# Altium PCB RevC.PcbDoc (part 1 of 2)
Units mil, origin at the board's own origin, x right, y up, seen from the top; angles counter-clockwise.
Board outline 3110.24 x 2539.37 mil, 2 copper layers (Top Layer, Bottom Layer); 147 components, 154 nets, 636 pads, 215 vias.
Unrouted connection lines stored in the file: 2.
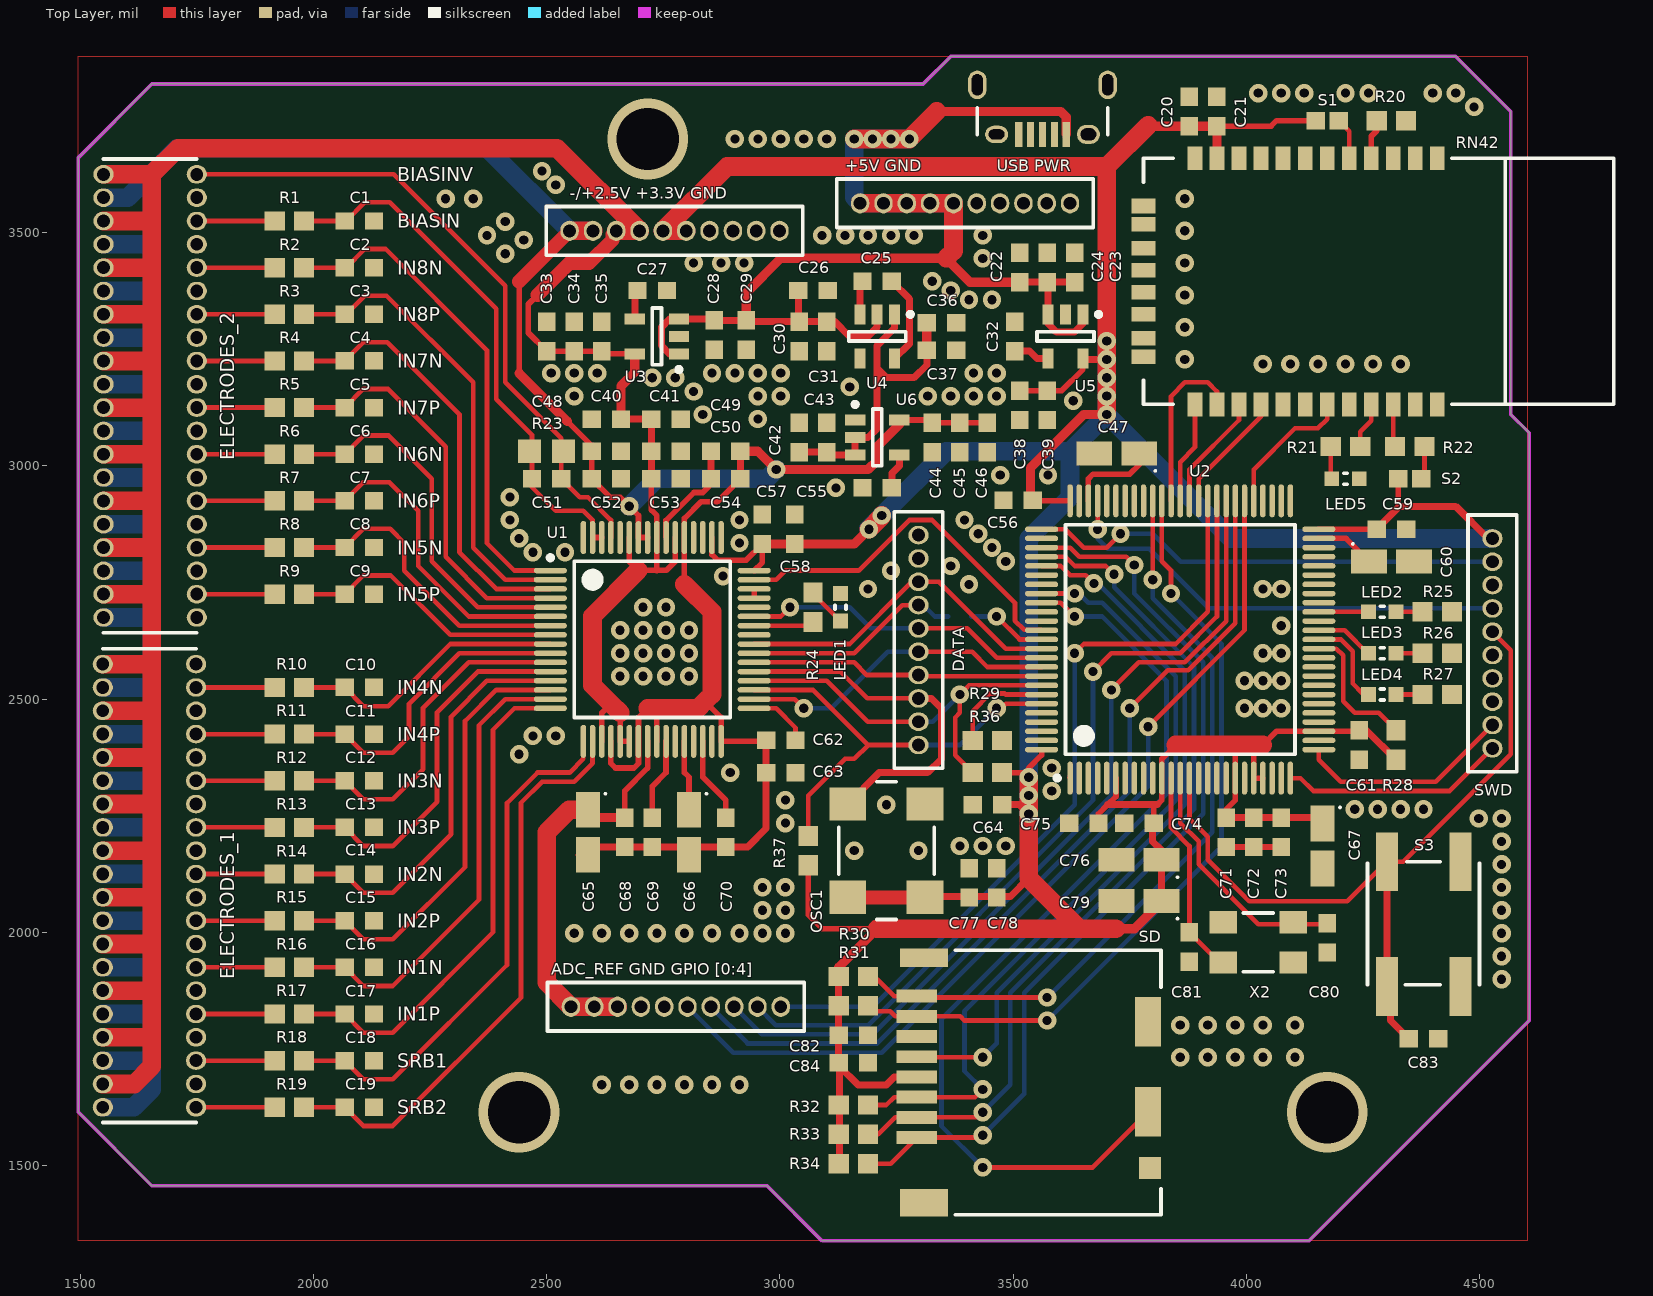
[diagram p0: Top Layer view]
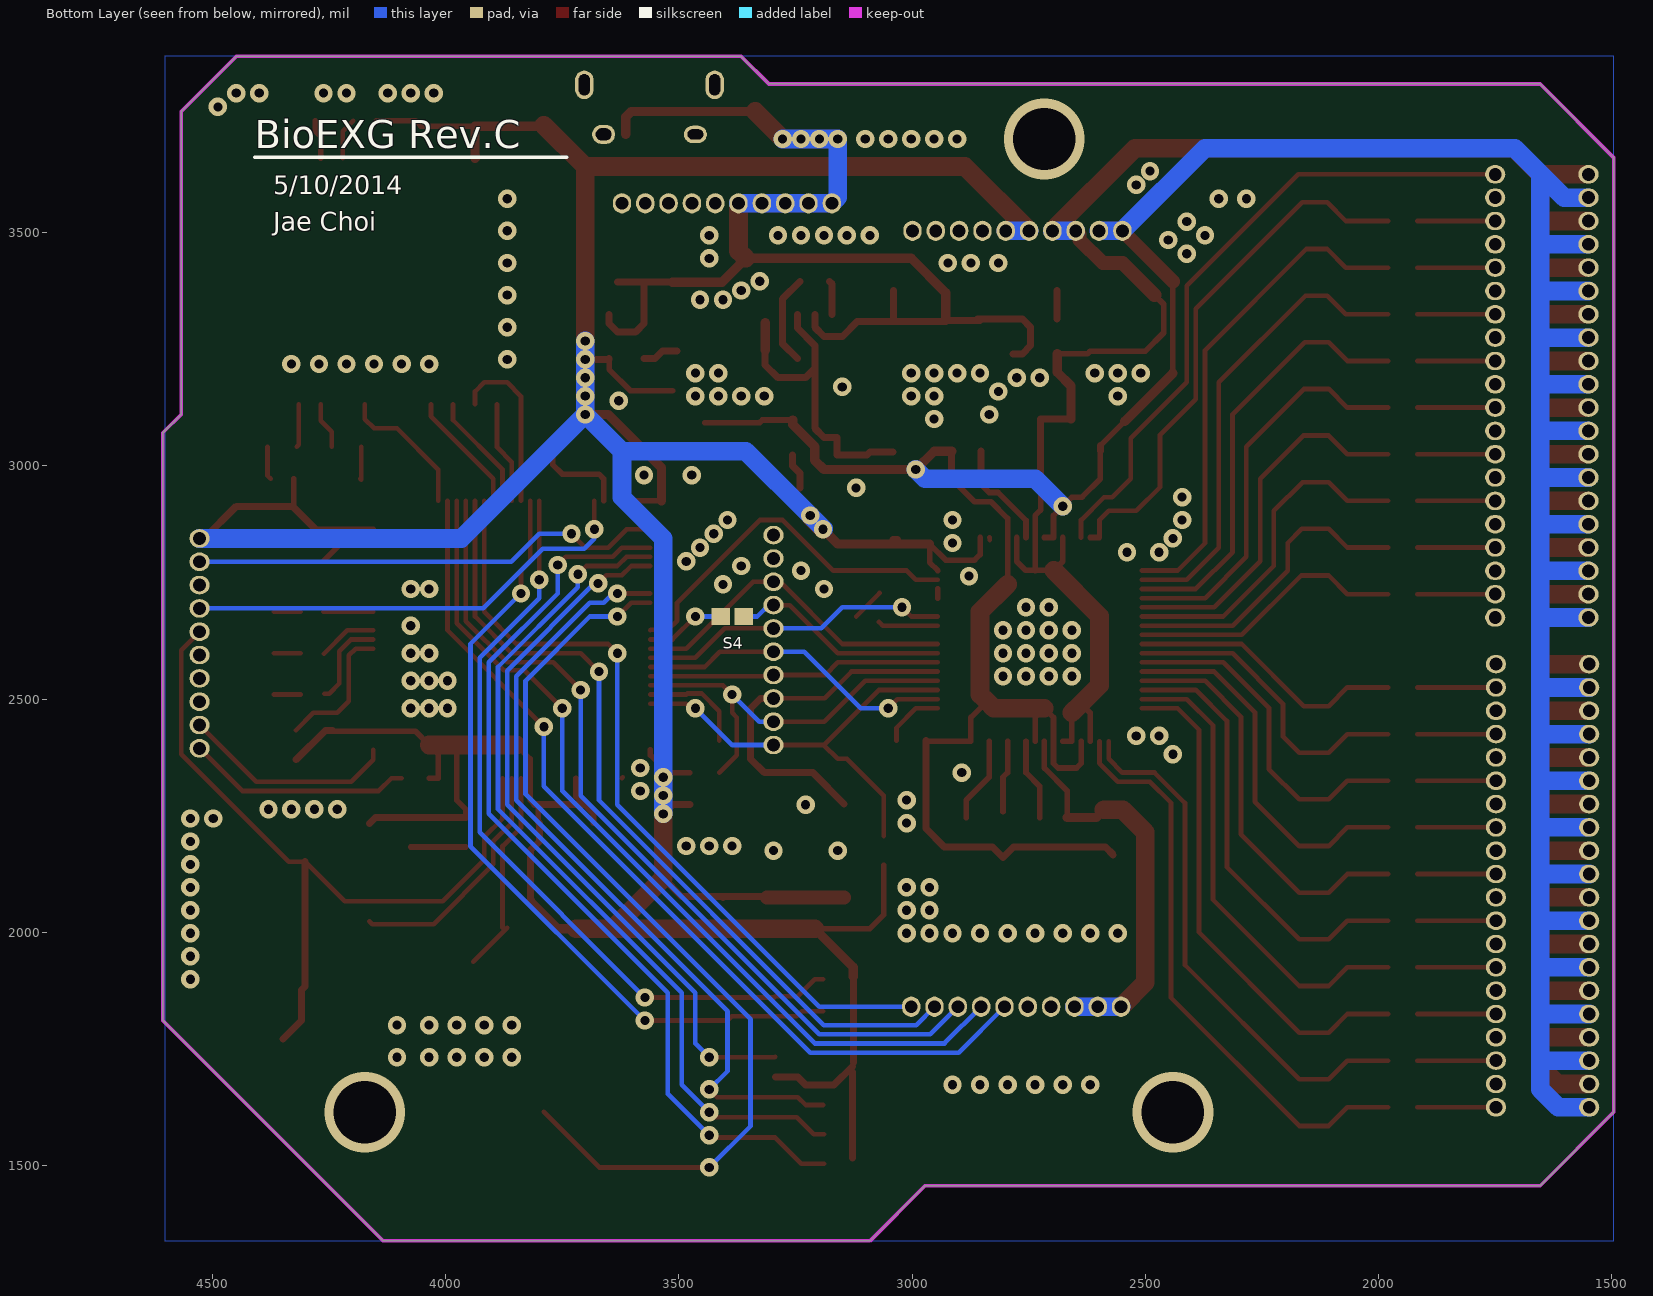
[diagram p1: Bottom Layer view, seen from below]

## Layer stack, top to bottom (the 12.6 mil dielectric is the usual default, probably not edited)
Top Solder: solder mask 0.4, Solder Resist, Dk 3.5
Top Layer: signal copper 1.4
Dielectric 1: dielectric 12.6, FR-4, Dk 4.8
Bottom Layer: signal copper 1.4
Bottom Solder: solder mask 0.4, Solder Resist, Dk 3.5

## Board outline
1653.54,3818.9 1496.06,3661.42 1496.06,1614.17 1653.54,1456.69 2972.44,1456.69 3090.55,1338.58 4133.86,1338.58 4606.3,1811.02 4606.3,3070.87 4566.93,3110.24 4566.93,3759.84 4448.82,3877.95 3366.14,3877.95 3307.09,3818.9

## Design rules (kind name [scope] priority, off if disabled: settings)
Clearance PullBack [InPoly and onLayer('GND') vs OnLayer('Keep-Out Layer')] p1: gap=10
Clearance [All] p2: gap=7
HoleSize [All] p1: absolutevalues=TRUE maxlimit=1000 minlimit=1 maxpercent=80.000 minpercent=20.000
MinimumSolderMaskSliver [All] p1: minsoldermaskwidth=4
PolygonConnect [IsPad] p1: connectstyle=Relief reliefconductorwidth=10 reliefentries=4 polygonreliefangle="90 Angle" airgapwidth=8
PolygonConnect Vias [IsVia] p2: connectstyle=Direct reliefconductorwidth=10 reliefentries=4 polygonreliefangle="90 Angle" airgapwidth=8
RoutingVias [All] p1: holewidth=19.68 width=39.37 viastyle="Through Hole" minholewidth=19.68 minwidth=39.37 maxholewidth=19.68 maxwidth=39.37
SilkToSilkClearance [All] p1: silktosilkclearance=1
SilkToSolderMaskClearance [IsPad] p1: minsilkscreentomaskgap=4 clearancetoexposedcopper=TRUE
SolderMaskExpansion OverExpansion_IC [(HasFootprint('STM-LQFP100_N') OR HasFootprint('TI-PAG64_N')) OR (HasFootprint('RN42') OR HasFootprint('USB_Micro_B'))] p1: expansion=5
SolderMaskExpansion [All] p2: expansion=3
Width [All] p1: maxlimit=100 minlimit=10 preferedwidth=10
26 further rules are at their usual default settings.

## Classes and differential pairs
component class F4_MODULE: C7_1 C20 C020_017 C020_019 C020_020 C020_031 C020_032 C020_034 C21 C22 C23 C24 C025_032 C027_022 C030_030 C030_033 C32 C033_032 C034_020 C034_030 C035_029 C035_032 C035_034 C037_020 C037_021 C037_030 C38 C038_037 C39 C039_022 C040_022 C041_019 C042_024 C47 C56 C59 C60 C61 C64 C67 C71 C72 C73 C74 C75 C76 C79 C80 C81 C82 C83 C84 CON025_035 JUMPER043_029 LED2 LED3 LED4 LED5 LED19 LED031_027 LED040_030 LED044_025 LED044_026 NI041_037 R3_1 R4_1 R5_1 R6_1 R10_1 R11_1 R12_1 R13_1 R15_1 R019_018 R019_022 R019_023 R019_032 R20 R21 R22 R25 R025_030 R26 R27 R28 R29 R30 R31 R32 R33 R34 R042_025 R043_037 RN1 RN040_033 RN42 S1 S2 S3 S3_1 SD SD035_016 U2 U5 U027_026 U038_026 "USB PWR" X2 X19 X040_019

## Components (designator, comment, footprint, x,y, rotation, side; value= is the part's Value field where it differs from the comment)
"+5V GND" "Value" M52-10 3172.05,3562.99 r0 top
"-/+2.5V +3.3V GND" "Value" M52-10 2549.21,3503.94 r0 top
"ADC_REF GND GPIO [0:4]" "Value" M52-10 3001.97,1840.55 r180 top
C1 "4.7nF" C0603 2098.43,3525 r0 top
C2 "4.7nF" C0603 2098.43,3425 r0 top
C3 "4.7nF" C0603 2098.43,3325 r0 top
C4 "4.7nF" C0603 2098.43,3225 r0 top
C5 "4.7nF" C0603 2098.43,3125 r0 top
C6 "4.7nF" C0603 2098.43,3025 r0 top
C7 "4.7nF" C0603 2098.43,2925 r0 top
C8 "4.7nF" C0603 2098.43,2825 r0 top
C9 "4.7nF" C0603 2098.43,2725 r0 top
C10 "4.7nF" C0603 2098.43,2525 r0 top
C11 "4.7nF" C0603 2098.43,2425 r0 top
C12 "4.7nF" C0603 2098.43,2325 r0 top
C13 "4.7nF" C0603 2098.43,2225 r0 top
C14 "4.7nF" C0603 2098.43,2125 r0 top
C15 "4.7nF" C0603 2098.43,2025 r0 top
C16 "4.7nF" C0603 2098.43,1925 r0 top
C17 "4.7nF" C0603 2098.43,1825 r0 top
C18 "4.7nF" C0603 2098.43,1725 r0 top
C19 "4.7nF" C0603 2098.43,1625 r0 top
C20 "0.1uF" C0603 3877.95,3759.84 r270 top
C21 "0.1uF" C0603 3937.01,3759.84 r270 top
C22 "1uF" C0603 3513.78,3425.2 r270 top
C23 "10uF" C0603 3572.83,3425.2 r270 top
C24 "10uF" C0603 3631.89,3425.2 r270 top
C25 "1uF" C0603 3208.66,3395.67 r0 top
C26 "10uF" C0603 3070.87,3375.98 r0 top
C27 "1uF" C0603 2726.38,3375.98 r0 top
C28 "1uF" C0603 2859.33,3280.59 r90 top
C29 "10uF" C0603 2928.23,3280.59 r90 top
C30 "10uF" C0603 3041.34,3277.56 r90 top
C31 "1uF" C0603 3100.39,3277.56 r90 top
C32 "1uF" C0603 3503.94,3277.56 r270 top
C33 "10uF" C0603 2500,3277.56 r270 top
C34 "2.2uF" C0603 2559.06,3277.56 r270 top
C35 "1uF" C0603 2618.11,3277.56 r270 top
C36 "10uF" C0603 3346.46,3307.09 r0 top
C37 "1uF" C0603 3346.46,3248.03 r0 top
C38 "2.2uF" C0603 3513.78,3129.92 r90 top
C39 "10uF" C0603 3572.83,3129.92 r90 top
C40 "1uF" C0603 2627.95,3100.39 r0 top
C41 "0.1uF" C0603 2755.91,3100.39 r0 top
C42 "10uF" C0603 3041.34,3061.02 r270 top
C43 "2.2uF" C0603 3100.39,3061.02 r270 top
C44 "1uF" C0603 3326.77,3061.02 r90 top
C45 "2.2uF" C0603 3385.83,3061.02 r90 top
C46 "10uF" C0603 3444.88,3061.02 r90 top
C47 "2.2uF" TCAXM8R 3722.32,3026.65 r180 top
C48 "1uF" C0603 2627.95,3031.5 r0 top
C49 "1uF" C0603 2755.91,3031.5 r0 top
C50 "1uF" C0603 2883.86,3031.5 r0 top
C51 "1.5nF" C0603 2500,2972.44 r0 top
C52 "0.1uF" C0603 2627.95,2972.44 r0 top
C53 "0.1uF" C0603 2755.91,2972.44 r0 top
C54 "0.1uF" C0603 2883.86,2972.44 r0 top
C55 "0.01uF" C0603 3208.66,2952.76 r0 top
C56 "0.1uF" C0603 3510.75,2926.06 r0 top
C57 "0.1uF" C0603 2962.6,2864.17 r270 top
C58 "1uF" C0603 3031.5,2864.17 r270 top
C59 "0.1uF" C0603 4311.02,2864.17 r0 top
C60 "2.2uF" TCAXM8R 4311.02,2795.28 r0 top
C61 "0.1uF" C0603 4242.13,2401.57 r90 top
C62 "0.1uF" C0603 3001.97,2411.42 r0 top
C63 "1uF" C0603 3001.97,2342.52 r0 top
C64 "0.1uF" C0603 3444.88,2273.62 r0 top
C65 "10uF" TCAXM8R 2588.58,2214.57 r270 top
C66 "100uF" TCAXM8R 2805.12,2214.57 r270 top
C67 "4.7uF" TCAXM8R 4163.39,2185.04 r270 top
C68 "0.1uF" C0603 2667.32,2214.57 r270 top
C69 "1uF" C0603 2726.38,2214.57 r270 top
C70 "1uF" C0603 2883.86,2214.57 r270 top
C71 "0.1uF" C0603 3956.69,2214.57 r90 top
C72 "0.1uF" C0603 4015.75,2214.57 r90 top
C73 "0.1uF" C0603 4074.8,2214.57 r90 top
C74 "0.1uF" C0603 3769.68,2234.25 r0 top
C75 "0.1uF" C0603 3651.57,2234.25 r0 top
C76 "1uF" TCAXM8R 3769.68,2155.51 r180 top
C77 "0.1uF" C0603 3405.51,2106.3 r270 top
C78 "1uF" C0603 3464.57,2106.3 r270 top
C79 "1uF" TCAXM8R 3769.68,2066.93 r180 top
C80 "9pF" C0603 4173.23,1988.19 r270 top
C81 "9pF" C0603 3877.95,1968.5 r270 top
C82 "0.1uF" C0603 3157.48,1779.53 r0 top
C83 "0.1uF" C0603 4379.92,1771.65 r0 top
C84 "0.1uF" C0603 3157.48,1720.47 r0 top
DATA "Value" M52-10 3297.24,2401.57 r90 top
ELECTRODES_1 "Value" M50-40 1648.43,2100 r270 top
ELECTRODES_2 "Value" M50-40 1650,3150 r270 top
LED1 "LSTS0603" LITEON_LED_0603 3129.92,2696.85 r90 top
LED2 "LSTS0603" LITEON_LED_0603 4291.34,2687.01 r0 top
LED3 "LSTS0603" LITEON_LED_0603 4291.34,2598.43 r0 top
LED4 "LSTS0603" LITEON_LED_0603 4291.34,2509.84 r0 top
LED5 "LSTS0603" LITEON_LED_0603 4212.6,2972.44 r0 top
OSC1 "FXO-HC736" HC73 3228.35,2175.2 r90 top
R1 "4.99K 1%" ERA3A 1948.43,3525 r0 top
R2 "4.99K 1%" ERA3A 1948.43,3425 r0 top
R3 "4.99K 1%" ERA3A 1948.43,3325 r0 top
R4 "4.99K 1%" ERA3A 1948.43,3225 r0 top
R5 "4.99K 1%" ERA3A 1948.43,3125 r0 top
R6 "4.99K 1%" ERA3A 1948.43,3025 r0 top
R7 "4.99K 1%" ERA3A 1948.43,2925 r0 top
R8 "4.99K 1%" ERA3A 1948.43,2825 r0 top
R9 "4.99K 1%" ERA3A 1948.43,2725 r0 top
R10 "4.99K 1%" ERA3A 1948.43,2525 r0 top
R11 "4.99K 1%" ERA3A 1948.43,2425 r0 top
R12 "4.99K 1%" ERA3A 1948.43,2325 r0 top
R13 "4.99K 1%" ERA3A 1948.43,2225 r0 top
R14 "4.99K 1%" ERA3A 1948.43,2125 r0 top
R15 "4.99K 1%" ERA3A 1948.43,2025 r0 top
R16 "4.99K 1%" ERA3A 1948.43,1925 r0 top
R17 "4.99K 1%" ERA3A 1948.43,1825 r0 top
R18 "4.99K 1%" ERA3A 1948.43,1725 r0 top
R19 "4.99K 1%" ERA3A 1948.43,1625 r0 top
R20 "10K" ERA3A 4311.02,3740.16 r0 top
R21 "100" ERA3A 4212.6,3041.34 r0 top
R22 "10K" ERA3A 4350.39,3041.34 r0 top
R23 "1M" ERA6A 2500,3031.5 r0 top
R24 "270" ERA3A 3070.87,2696.85 r90 top
R25 "270" ERA3A 4409.45,2687.01 r0 top
R26 "270" ERA3A 4409.45,2598.43 r0 top
R27 "100" ERA3A 4409.45,2509.84 r0 top
R28 "10K" ERA3A 4320.87,2401.57 r90 top
R29 "10K" ERA3A 3444.88,2411.42 r180 top
R30 "47K" ERA3A 3157.48,1905.51 r0 top
R31 "47K" ERA3A 3157.48,1842.52 r0 top
R32 "47K" ERA3A 3157.48,1629.92 r0 top
R33 "47K" ERA3A 3157.48,1566.93 r0 top
R34 "47K" ERA3A 3157.48,1503.94 r0 top
R36 "10K" ERA3A 3444.88,2342.52 r0 top
R37 "10K" ERA3A 3061.02,2175.2 r270 top
RN42 "RN42" RN42 4094.49,3395.67 r270 top
S1 "Value" JUMPER 4173.23,3740.16 r0 top
S2 "Value" JUMPER 4350.39,2972.44 r180 top
S3 "EVQQ2" EVQQ2 4379.92,2017.72 r270 top
S4 "Value" JUMPER 3385.83,2677.17 r0 bottom
SD "DM3CS" DM3CS 3543.31,1683.07 r270 top
SWD "Value" M52-10 4527.56,2844.49 r270 top
U1 "ADS1299" TI-PAG64_N 2726.38,2627.95 r0 top
U2 "STM32F407" STM-LQFP100_N 3858.27,2627.95 r90 top
U3 "TPS73225" TI-DBV5_N 2736.22,3277.56 r180 top
U4 "TPS6040X" TI-DBV5_N 3208.66,3277.56 r270 top
U5 "TPS73233" TI-DBV5_N 3612.2,3277.56 r270 top
U6 "TPS72325" TI-DBV5_N 3208.66,3061.02 r0 top
"USB PWR" "FCI_USB_MicroB" USB_Micro_B 3562.99,3710.63 r180 top
X2 "16.00 Mhz" 405XO 4025.59,1978.35 r180 top

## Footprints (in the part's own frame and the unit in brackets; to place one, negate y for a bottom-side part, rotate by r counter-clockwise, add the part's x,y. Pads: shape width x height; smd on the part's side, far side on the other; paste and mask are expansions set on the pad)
405XO [mm] "CTS 405 Series Crystal Oscillator"
  rect 1.5x1.2 smd: 1(-1.9,-1.1) 2(1.9,-1.1) 3(1.9,1.1) 4(-1.9,1.1)
  silkscreen extent -0.8,-1.6 0.8,1.6, body extent -1.6,-1.25 1.6,1.25, height 1.07
C0603 [mm] "Kemet C0603 Ceramic Capacitor"
  rect 1x0.95 smd paste-254: 1(-0.8,0) 2(0.8,0)
  body extent -0.88,-0.48 0.87,0.48, height 0.87
DM3CS [mm] "DM3CS Micro SD Card Holder"
  rect 0.7x2.2 smd: 1(3.125,-6.35) 2(2.025,-6.35) 3(0.925,-6.35) 4(-0.175,-6.35) 5(-1.275,-6.35) 6(-2.375,-6.35) 7(-3.475,-6.35) 8(-4.575,-6.35)
  rect 1x2.6 smd: 6(-6.675,-5.95)
  rect 2.7x1.4 smd: 6(-3.175,6.25) 9(1.725,6.25)
  rect 1.2x1.2 smd: 6(4.775,6.35)
  rect 1.5x2.6 smd: 6(6.675,-5.95)
  silkscreen extent -7.07,-4.25 7.33,6.95, body extent -6.8,-7.15 7,6.95, height 1.88
ERA3A [mm] "ERA3A Panasonic Thin Film Resistor 0603"
  rect 1.1x1.05 smd: 1(-0.8,0) 2(0.8,0)
  body extent -0.9,-0.5 0.9,0.5, height 0.55
ERA6A [mm] "ERA6A Panasonic Thin Film Resistor 0805"
  rect 1.25x1.3 smd: 1(-0.925,0) 2(0.925,0)
  body extent -1.1,-0.67 1.1,0.68, height 0.6
EVQQ2 [mm] "Panasonic EVQQ2 Tactile Button"
  rect 3.2x1.2 smd: A(-3.4,-2) A(3.4,-2) B(-3.4,2) B(3.4,2)
  silkscreen extent -3.4,-3.05 3.3,3.05
HC73 [mm] "FXO HC73 Series Oscillator"
  rect 1.8x2 smd: 1(-2.54,-2.1) 2(2.54,-2.1) 3(2.54,2.1) 4(-2.54,2.1)
  silkscreen extent -3.75,-2.6 3.75,2.6, body extent -3.75,-2.62 3.75,2.6, height 1.4
JUMPER [mm] "Jumper"
  rect 1x0.95 smd mask+0.127: 1(-0.625,0) 2(0.625,0)
LITEON_LED_0603 [mm]
  rect 0.8x0.8 smd: 1(-0.75,0) 2(0.75,0)
  silkscreen extent -0.1,-0.3 0.1,0.3, body extent -0.85,-0.45 0.85,0.45, height 0.45
M50-40 [mm] "M50 Series Female Header Connector"
  oval 1x1.1 hole 0.7: 1(-12.065,-2.54) 2(-10.795,-2.54) 3(-9.525,-2.54) 4(-8.255,-2.54) 5(-6.985,-2.54) 6(-5.715,-2.54) 7(-4.445,-2.54) 8(-3.175,-2.54) 9(-1.905,-2.54) 10(-0.635,-2.54) 11(0.635,-2.54) 12(1.905,-2.54) 13(3.175,-2.54) 14(4.445,-2.54) 15(5.715,-2.54) 16(6.985,-2.54) 17(8.255,-2.54) 18(9.525,-2.54) 19(10.795,-2.54) 20(12.065,-2.54) 21(12.065,2.54) 22(10.795,2.54) 23(9.525,2.54) 24(8.255,2.54) 25(6.985,2.54) 26(5.715,2.54) 27(4.445,2.54) 28(3.175,2.54) 29(1.905,2.54) 30(0.635,2.54) 31(-0.635,2.54) 32(-1.905,2.54) 33(-3.175,2.54) 34(-4.445,2.54) 35(-5.715,2.54) 36(-6.985,2.54) 37(-8.255,2.54) 38(-9.525,2.54) 39(-10.795,2.54) 40(-12.065,2.54)
  silkscreen extent -12.9,-2.54 12.9,2.54, body extent -12.9,-2.54 12.9,2.54, height 4
M52-10 [mm] "M52 Series Connector 10 Pin"
  oval 1x1.1 hole 0.7: 1(0,0) 2(1.27,0) 3(2.54,0) 4(3.81,0) 5(5.08,0) 6(6.35,0) 7(7.62,0) 8(8.89,0) 9(10.16,0) 10(11.43,0)
  silkscreen extent -1.27,-1.33 12.7,1.33, body extent -0.64,-0.64 12.06,0.62, height 4.3
RN42 [mm] "RN42 Bluetooth Transciever"
  rect 1.3x0.8 smd: 1(-6.7,8) 2(-6.7,6.8) 3(-6.7,5.6) 4(-6.7,4.4) 5(-6.7,3.2) 6(-6.7,2) 7(-6.7,0.8) 8(-6.7,-0.4) 9(-6.7,-1.6) 10(-6.7,-2.8) 11(-6.7,-4) 12(-6.7,-5.2) 13(6.7,-5.2) 14(6.7,-4) 15(6.7,-2.8) 16(6.7,-1.6) 17(6.7,-0.4) 18(6.7,0.8) 19(6.7,2) 20(6.7,3.2) 21(6.7,4.4) 22(6.7,5.6) 23(6.7,6.8) 24(6.7,8)
  rect 0.8x1.3 smd: 28(3.1,-8) 29(-3.1,-8) 30(4.1,-8) 31(1.8,-8) 32(0.6,-8) 33(-0.6,-8) 34(-1.8,-8) 35(-4.1,-8)
  silkscreen extent -6.7,-8 6.7,17.6, body extent -6.7,-8 6.7,17.8, height 2.12
STM-LQFP100_N [mm] "Thin QFP, 100-Leads, Body 14x14mm, Pitch 0.5mm, IPC Medium Density"
  oval 1.8x0.3 smd: 1(-7.55,6) 2(-7.55,5.5) 3(-7.55,5) 4(-7.55,4.5) 5(-7.55,4) 6(-7.55,3.5) 7(-7.55,3) 8(-7.55,2.5) 9(-7.55,2) 10(-7.55,1.5) 11(-7.55,1) 12(-7.55,0.5) 13(-7.55,0) 14(-7.55,-0.5) 15(-7.55,-1) 16(-7.55,-1.5) 17(-7.55,-2) 18(-7.55,-2.5) 19(-7.55,-3) 20(-7.55,-3.5) 21(-7.55,-4) 22(-7.55,-4.5) 23(-7.55,-5) 24(-7.55,-5.5) 25(-7.55,-6) 51(7.55,-6) 52(7.55,-5.5) 53(7.55,-5) 54(7.55,-4.5) 55(7.55,-4) 56(7.55,-3.5) 57(7.55,-3) 58(7.55,-2.5) 59(7.55,-2) 60(7.55,-1.5) 61(7.55,-1) 62(7.55,-0.5) 63(7.55,0) 64(7.55,0.5) 65(7.55,1) 66(7.55,1.5) 67(7.55,2) 68(7.55,2.5) 69(7.55,3) 70(7.55,3.5) 71(7.55,4) 72(7.55,4.5) 73(7.55,5) 74(7.55,5.5) 75(7.55,6)
  oval 0.3x1.8 smd: 26(-6,-7.55) 27(-5.5,-7.55) 28(-5,-7.55) 29(-4.5,-7.55) 30(-4,-7.55) 31(-3.5,-7.55) 32(-3,-7.55) 33(-2.5,-7.55) 34(-2,-7.55) 35(-1.5,-7.55) 36(-1,-7.55) 37(-0.5,-7.55) 38(0,-7.55) 39(0.5,-7.55) 40(1,-7.55) 41(1.5,-7.55) 42(2,-7.55) 43(2.5,-7.55) 44(3,-7.55) 45(3.5,-7.55) 46(4,-7.55) 47(4.5,-7.55) 48(5,-7.55) 49(5.5,-7.55) 50(6,-7.55) 76(6,7.55) 77(5.5,7.55) 78(5,7.55) 79(4.5,7.55) 80(4,7.55) 81(3.5,7.55) 82(3,7.55) 83(2.5,7.55) 84(2,7.55) 85(1.5,7.55) 86(1,7.55) 87(0.5,7.55) 88(0,7.55) 89(-0.5,7.55) 90(-1,7.55) 91(-1.5,7.55) 92(-2,7.55) 93(-2.5,7.55) 94(-3,7.55) 95(-3.5,7.55) 96(-4,7.55) 97(-4.5,7.55) 98(-5,7.55) 99(-5.5,7.55) 100(-6,7.55)
  silkscreen extent -7.67,-6.25 6.25,6.82, body extent -8,-8 8,8, height 1.2
TCAXM8R [mm] "TCA Tantalum Capacitor 1206 Rohm"
  rect 1.95x1.3 smd: 1(-1.225,0) 2(1.225,0)
  silkscreen extent -2.15,0.9 -2.05,1, body extent -1.7,-0.9 1.7,0.9, height 1.8
TI-DBV5_N [mm] "SOT23, 5-Leads, Body 2.9x1.6mm, Pitch 0.95mm, IPC Medium Density"
  rect 1.1x0.6 smd: 1(-1.2,0.95) 2(-1.2,0) 3(-1.2,-0.95) 4(1.2,-0.95) 5(1.2,0.95)
  silkscreen extent -1.33,-1.55 0.25,1.92, body extent -1.51,-1.52 1.51,1.53, height 1.6
TI-PAG64_N [mm] "QFP, 64-Leads, Body 10x10mm, Pitch 0.5mm, IPC Medium Density"
  oval 1.8x0.3 smd: 1(-5.55,3.75) 2(-5.55,3.25) 3(-5.55,2.75) 4(-5.55,2.25) 5(-5.55,1.75) 6(-5.55,1.25) 7(-5.55,0.75) 8(-5.55,0.25) 9(-5.55,-0.25) 10(-5.55,-0.75) 11(-5.55,-1.25) 12(-5.55,-1.75) 13(-5.55,-2.25) 14(-5.55,-2.75) 15(-5.55,-3.25) 16(-5.55,-3.75) 33(5.55,-3.75) 34(5.55,-3.25) 35(5.55,-2.75) 36(5.55,-2.25) 37(5.55,-1.75) 38(5.55,-1.25) 39(5.55,-0.75) 40(5.55,-0.25) 41(5.55,0.25) 42(5.55,0.75) 43(5.55,1.25) 44(5.55,1.75) 45(5.55,2.25) 46(5.55,2.75) 47(5.55,3.25) 48(5.55,3.75)
  oval 0.3x1.8 smd: 17(-3.75,-5.55) 18(-3.25,-5.55) 19(-2.75,-5.55) 20(-2.25,-5.55) 21(-1.75,-5.55) 22(-1.25,-5.55) 23(-0.75,-5.55) 24(-0.25,-5.55) 25(0.25,-5.55) 26(0.75,-5.55) 27(1.25,-5.55) 28(1.75,-5.55) 29(2.25,-5.55) 30(2.75,-5.55) 31(3.25,-5.55) 32(3.75,-5.55) 49(3.75,5.55) 50(3.25,5.55) 51(2.75,5.55) 52(2.25,5.55) 53(1.75,5.55) 54(1.25,5.55) 55(0.75,5.55) 56(0.25,5.55) 57(-0.25,5.55) 58(-0.75,5.55) 59(-1.25,5.55) 60(-1.75,5.55) 61(-2.25,5.55) 62(-2.75,5.55) 63(-3.25,5.55) 64(-3.75,5.55)
  silkscreen extent -5.67,-4.25 4.25,4.57, body extent -6,-5.97 6,6.03, height 1.2
USB_Micro_B [mm] "FCI USB Micro B Connector"
  rect 0.4x1.35 smd: 1(-1.3,0) 2(-0.65,0) 3(0,0) 4(0.65,0) 5(1.3,0)
  oval 1x1.55 hole 0.6 slot 1.15 at 90 deg: 6(-3.55,-2.7) 6(3.55,-2.7)
  oval 1.25x1.05 hole 0.65 slot 0.85 at 0 deg: 6(-2.5,0)
  oval 1.25x0.95 hole 0.55 slot 0.85 at 0 deg: 6(2.5,0)
  silkscreen extent -3.55,-1.45 3.55,0

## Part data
"+5V GND" "-/+2.5V +3.3V GND" "ADC_REF GND GPIO [0:4]" DATA SWD: library part M52-10, "M52 Series Female Header Connector"
C1 C2 C3 C4 C5 C6 C7 C8 C9 C10 C11 C12 C13 C14 C15 C16 C17 C18 C19 C20 C21 C22 C23 C24 C25 C26 C27 C28 C29 C30 C31 C32 C33 C34 C35 C36 C37 C38 C39 C40 C41 C42 C43 C44 C45 C46 C48 C49 C50 C51 C52 C53 C54 C55 C56 C57 C58 C59 C61 C62 C63 C64 C68 C69 C70 C71 C72 C73 C74 C75 C77 C78 C80 C81 C82 C83 C84: library part CAP, "Capacitor Non Polarized"
C47 C60 C65 C66 C67 C76 C79: library part CAP_POL, "Polarized Capacitor - Tantalum"
ELECTRODES_1 ELECTRODES_2: library part M50-40, "M50 Series Female Header Connector"
LED1 LED2 LED3 LED4 LED5: library part "LITEON LED", "LITE ON LED 0603"
OSC1: library part FXO-HC73, "FXO-HC73 Series Oscillator"
R1 R2 R3 R4 R5 R6 R7 R8 R9 R10 R11 R12 R13 R14 R15 R16 R17 R18 R19 R20 R21 R22 R23 R24 R25 R26 R27 R28 R29 R30 R31 R32 R33 R34 R36 R37: library part RES, "Resistor"
RN42: "RN42 Bluetooth Transciever"
S1 S2 S4: library part JMP, "Jumper"
S3: library part "EVQQ2 Tactile Button", "EVQQ2 Tactile Button"
SD: "DM3CS Micro SD Card Holder"
U1: library part TI-ADS1299-PAG-64, "The Famous ADS1299 :)"
U2: "STM32F407 32 bit Microcontroller"
U3 U5: library part TI-TPS73225-DVB5, "TPS73225/TPS73233 Voltage Regulator"
U4: library part TI-TPS6040X-DBV5, "TPS6040X Voltage Inverter"
U6: library part TI-TPS72325-DBV5, "TPS72325 Negative Voltage Regulator"
"USB PWR": "FCI USB Micro B"
X2: library part CTS-405, "CTS 405 Series Crystal Oscillator"

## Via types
v1: diameter 39.37, hole 19.68, Top Layer to Bottom Layer, 212 vias
v2: diameter 173.23, hole 133.86, Top Layer to Bottom Layer, 3 vias

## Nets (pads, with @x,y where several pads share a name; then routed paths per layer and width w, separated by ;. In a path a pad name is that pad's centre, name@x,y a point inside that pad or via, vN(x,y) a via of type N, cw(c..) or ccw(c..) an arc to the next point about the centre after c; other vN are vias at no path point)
+2.5V: "-/+2.5V +3.3V GND.3" "-/+2.5V +3.3V GND.4" C33.2 C34.2 C35.2 C40.2 C41.1 C49.1 C53.1 ELECTRODES_1.1 ELECTRODES_1.3 ELECTRODES_1.5 ELECTRODES_1.7 ELECTRODES_1.9 ELECTRODES_1.11 ELECTRODES_1.13 ELECTRODES_1.15 ELECTRODES_1.17 ELECTRODES_1.19 ELECTRODES_2.1 ELECTRODES_2.3 ELECTRODES_2.5 ELECTRODES_2.7 ELECTRODES_2.9 ELECTRODES_2.11 ELECTRODES_2.13 ELECTRODES_2.15 ELECTRODES_2.17 ELECTRODES_2.19 U1.19 U1.21 U1.22 U1.54 U1.56 U1.59 U3.5 | length 7094.7
  Top Layer w12: 2480.32,3366.14 2460.63,3346.46 2460.63,3285.43 C33.2@2500,3246.06 C34.2@2559.06,3246.06 C35.2@2618.11,3246.06 2624.02,3240.16 U3.5@2688.98,3240.16 ; U1.19@2618.11,2409.45 2618.11,2470.47 2637.8,2490.16 ; 2657.48,2470.47 U1.21@2657.48,2409.45 U1.22@2677.17,2409.45 ; U1.59@2677.17,2846.46 2677.17,2795.28 2696.43,2776.01 2736.22,2776.01 ; C53.1@2724.41,2972.44 2724.41,2905.51 2736.22,2893.7 U1.56@2736.22,2846.46 2736.22,2795.28 2736.22,2776.01 ; 2736.22,2775.59 2736.22,2776.01 ; U1.54@2775.59,2846.46 2775.59,2795.28 2756.33,2776.01 2736.22,2776.01
  Top Layer w15: C40.2@2659.45,3100.39 C41.1@2724.41,3100.39 C53.1@2724.41,2972.44
  Top Layer w20: C40.2@2659.45,3100.39 2659.45,3171.26 2688.98,3200.79 U3.5@2688.98,3240.16
  Top Layer w30: 2480.32,3366.14 2549.21,3435.04 2591.23,3435.04 2640.9,3484.7 2640.9,3486.23 2641.21,3486.54 2641.21,3495.94 2649.21,3503.94
  Top Layer w40: ELECTRODES_1.19@1548.43,1675 1615.94,1675 1653.54,1712.6 1653.54,1771.65 ; ELECTRODES_1.17@1548.43,1775 1650.2,1775 1653.54,1771.65 ; ELECTRODES_1.15@1548.43,1875 1650.2,1875 ; ELECTRODES_1.13@1548.43,1975 1650.2,1975 ; ELECTRODES_1.11@1548.43,2075 1650.2,2075 ; ELECTRODES_1.9@1548.43,2175 1650.2,2175 ; ELECTRODES_1.7@1548.43,2275 1650.2,2275 ; ELECTRODES_1.5@1548.43,2375 1650.2,2375 ; ELECTRODES_1.3@1548.43,2475 1650.2,2475 ; ELECTRODES_1.1@1548.43,2575 1649.8,2575 1653.54,2578.74 ; ELECTRODES_2.19@1550,2725 1651.77,2725 ; ELECTRODES_2.17@1550,2825 1651.77,2825 ; ELECTRODES_2.15@1550,2925 1651.77,2925 ; ELECTRODES_2.13@1550,3025 1651.77,3025 ; ELECTRODES_2.11@1550,3125 1651.77,3125 ; ELECTRODES_2.9@1550,3225 1651.77,3225 ; ELECTRODES_2.7@1550,3325 1651.77,3325 ; ELECTRODES_2.5@1550,3425 1651.77,3425 ; ELECTRODES_2.3@1550,3525 1652.17,3525 1653.54,3523.62 ; ELECTRODES_2.1@1550,3625 1653.54,3625 ; 2649.21,3503.94 2699.21,3503.94 2522.05,3681.1 1709.65,3681.1 1653.54,3625 ; 2657.48,2470.47 2637.8,2490.16 2598.43,2529.53 2598.43,2678.01 2696.43,2776.01 ; 1653.54,1771.65 1653.54,2578.74 ; 1653.54,2578.74 1653.54,3523.62 ; 1653.54,3523.62 1653.54,3625
  Bottom Layer w40: 2649.21,3503.94 2699.21,3503.94
+3.3V: "-/+2.5V +3.3V GND.5" "-/+2.5V +3.3V GND.6" C20.2 C21.2 C38.2 C39.2 C56.2 C57.2 C58.2 C59.1 C61.2 C64.2 C67.1 C71.2 C72.2 C73.2 C74.2 C75.2 C76.1 C77.2 C78.2 C79.1 C82.1 C84.1 OSC1.1 OSC1.4 R28.1 R30.1 R31.1 R32.1 R33.1 R34.1 R36.2 R37.2 RN42.11 S1.1 S2.2 SD.4 SWD.1 U1.48 U1.50 U2.6 U2.11 U2.19 U2.21 U2.22 U2.28 U2.50 U2.75 U2.100 U5.5 | length 10441.7
  Top Layer w12: U1.50@2854.33,2846.46 2854.33,2809.88 2866.18,2798.02 2927.94,2798.02 C57.2@2962.6,2832.68 2962.6,2793.31 U1.48@2944.88,2775.59 ; R37.2@3061.02,2143.7 3061.02,2037.4 3090.55,2007.87 3208.66,2007.87 ; R36.2@3476.38,2342.52 3523.62,2342.52 v1(3533.46,2332.68) 3533.46,2352.36 3561.02,2379.92 U2.100@3561.02,2391.73 ; C38.2@3513.78,3161.42 C39.2@3572.83,3161.42 3604.33,3161.42 3649.61,3206.69 U5.5@3649.61,3228.35 ; C56.2@3537.4,2925.2 U2.75@3622.05,2925.2 ; C75.2@3683.07,2234.25 3683.07,2253.94 3702.76,2273.62 3720.47,2291.34 U2.6@3720.47,2330.71 ; C74.2@3801.18,2234.25 3801.18,2265.75 ; 3809.05,2273.62 3818.9,2283.46 U2.11@3818.9,2330.71 3818.9,2372.05 3848.43,2401.57 ; C21.2@3937.01,3728.35 4053.15,3728.35 4064.96,3740.16 S1.1@4148.62,3740.16 ; C71.2@3956.69,2246.06 3956.69,2263.78 3976.38,2283.46 U2.19@3976.38,2330.71 3976.38,2401.57 ; U2.22@4035.43,2330.71 U2.21@4015.75,2330.71 4015.75,2381.89 4035.43,2401.57 4064.96,2431.1 U2.28@4155.51,2431.1 4240.16,2431.1 C61.2@4242.13,2433.07 ; U2.50@4155.51,2864.17 C59.1@4279.53,2864.17 ; S2.2@4325.79,2972.44 4325.79,2916.19 4328.59,2913.39
  Top Layer w15: C58.2@3031.5,2842.52 C58.2@3041.34,2842.52 ; C84.1@3125.98,1720.47 C82.1@3125.98,1779.53 R31.1@3125.98,1842.52 R30.1@3125.98,1905.51 ; R34.1@3127.95,1515.75 3127.95,1700.79 ; C84.1@3127.95,1712.6 3167.32,1673.23 3228.35,1673.23 3245.08,1689.96 SD.4@3293.31,1689.96 ; OSC1.1@3311.02,2075.2 3312.6,2076.77 C77.2@3403.54,2076.77 ; C77.2@3405.51,2074.8 3405.51,2076.77 3494.09,2076.77 3533.46,2116.14 ; C64.2@3476.38,2273.62 3513.78,2273.62 v1(3533.46,2253.94) ; U5.5@3649.61,3230.32 3649.61,3228.35 v1(3700.79,3228.35) ; 3702.76,2273.62 3809.05,2273.62 ; C74.2@3799.21,2234.25 3799.21,2194.88 3817.91,2176.18 C76.1@3817.91,2155.51 C79.1@3817.91,2066.93 ; C71.2@3956.69,2246.06 C72.2@4015.75,2246.06 C73.2@4074.8,2246.06 4150.59,2246.06 C67.1@4163.39,2233.27 ; C61.2@4242.13,2433.07 4257.87,2433.07 R28.1@4320.87,2370.08 ; C59.1@4279.53,2864.17 4279.53,2864.33 4328.59,2913.39 4448.82,2913.39 4517.72,2844.49 SWD.1@4527.56,2844.49
  Top Layer w20: C57.2@2962.6,2832.68 C58.2@3031.5,2832.68 3159.45,2832.68 v1(3190.94,2864.17) ; R30.1@3125.98,1905.51 3125.98,1925.2 3208.66,2007.87 ; C56.2@3537.4,2925.2 3537.4,2996.06 3651.57,3110.24 v1(3700.79,3110.24) ; 3720.47,2007.87 3760.32,2007.87 3817.91,2065.47 C79.1@3817.91,2066.93 ; 3789.37,3730.32 3791.34,3728.35 C20.2@3877.95,3728.35 C21.2@3937.01,3728.35 3937.01,3663.39 3935.04,3661.42 RN42.11@3937.01,3659.45
  Top Layer w30: OSC1.4@3145.67,2075.2 OSC1.1@3311.02,2075.2
  Top Layer w40: 2799.21,3503.94 2749.21,3503.94 2887.01,3641.73 3700.79,3641.73 ; v1(3190.94,2864.17) 3218.5,2891.73 v1(3218.5,2893.7) ; 3208.66,2007.87 3641.73,2007.87 ; v1(3533.46,2332.68) v1(3533.46,2293.31) v1(3533.46,2253.94) 3533.46,2116.14 3641.73,2007.87 ; v1(3700.79,3110.24) v1(3700.79,3149.61) v1(3700.79,3188.98) v1(3700.79,3228.35) v1(3700.79,3267.72) 3700.79,3641.73 ; 3720.47,2007.87 3641.73,2007.87 ; 3789.37,3730.32 3700.79,3641.73 ; 3848.43,2401.57 3976.38,2401.57 4035.43,2401.57
  Bottom Layer w40: 2749.21,3503.94 2799.21,3503.94 ; v1@3189.96,2865.16 v1(3218.5,2893.7) 3356.3,3031.5 3622.05,3031.5 ; v1(3533.46,2253.94) v1(3533.46,2293.31) v1(3533.46,2332.68) 3533.46,2844.49 3622.05,2933.07 3622.05,3031.5 ; v1(3700.79,3267.72) v1(3700.79,3228.35) v1(3700.79,3188.98) v1(3700.79,3149.61) v1(3700.79,3110.24) ; SWD.1@4527.56,2844.49 3966.54,2844.49 v1(3700.79,3110.24) ; 3622.05,3031.5 v1(3700.79,3110.24)
+5V: "+5V GND.1" "+5V GND.2" "+5V GND.3" "+5V GND.4" "+5V GND.5" "USB PWR.1" C22.2 C23.2 C24.2 C26.1 C28.2 C29.2 C30.2 C31.2 U3.1 U3.3 U4.2 U5.1 U5.3 | length 2995.8
  Top Layer w12: C30.2@3039.37,3311.02 C30.2@3041.34,3309.06
  Top Layer w15: U3.1@2783.46,3240.16 2763.78,3240.16 2746.06,3257.87 2746.06,3297.24 2763.78,3314.96 U3.3@2783.46,3314.96 C28.2@2859.33,3314.96 ; C28.2@2854.33,3312.09 C28.2@2859.33,3312.09 C29.2@2928.23,3312.09 ; C29.2@2928.23,3309.06 C30.2@3041.34,3309.06 C31.2@3100.39,3309.06 3118.11,3309.06 3149.61,3277.56 3188.98,3277.56 3208.66,3297.24 U4.2@3208.66,3324.8 ; C30.2@3039.37,3311.02 C26.1@3039.37,3375.98 ; C22.2@3513.78,3393.7 C23.2@3572.83,3393.7 ; C24.2@3631.89,3393.7 C23.2@3572.83,3393.7 ; U5.1@3649.61,3324.8 3649.61,3305.12 3631.89,3287.4 3592.52,3287.4 3574.8,3305.12 3574.8,3391.73 C23.2@3572.83,3393.7
  Top Layer w20: C29.2@2928.23,3312.09 2928.23,3371.14 3001.97,3444.88 3356.3,3444.88 3407.48,3393.7 C22.2@3513.78,3393.7 ; 3336.61,3759.84 3602.36,3759.84 3614.17,3748.03 3614.17,3710.63
  Top Layer w40: v1(3159.45,3700.79) v1(3198.82,3700.79) v1(3238.19,3700.79) v1(3277.56,3700.79) 3336.61,3759.84 ; 3172.05,3562.99 3222.05,3562.99 3272.05,3562.99 3322.05,3562.99 3372.05,3562.99 3372.05,3460.63 3356.3,3444.88
  Bottom Layer w40: v1(3277.56,3700.79) v1(3238.19,3700.79) v1(3198.82,3700.79) v1(3159.45,3700.79) 3159.45,3575.59 3172.05,3562.99 3222.05,3562.99 3272.05,3562.99 3322.05,3562.99 3372.05,3562.99
-2.5V: "-/+2.5V +3.3V GND.1" "-/+2.5V +3.3V GND.2" C44.2 C45.2 C46.2 C48.1 C50.2 C52.1 C54.2 C62.1 C63.1 C65.2 C66.2 C68.2 C69.2 C70.2 ELECTRODES_1.2 ELECTRODES_1.4 ELECTRODES_1.6 ELECTRODES_1.8 ELECTRODES_1.10 ELECTRODES_1.12 ELECTRODES_1.14 ELECTRODES_1.16 ELECTRODES_1.18 ELECTRODES_1.20 ELECTRODES_2.2 ELECTRODES_2.4 ELECTRODES_2.6 ELECTRODES_2.8 ELECTRODES_2.10 ELECTRODES_2.12 ELECTRODES_2.14 ELECTRODES_2.16 ELECTRODES_2.18 ELECTRODES_2.20 U1.20 U1.23 U1.25 U1.32 U1.53 U1.57 U1.58 U6.5 | length 8866.9
  Top Layer w12: 2440.94,3198.82 2440.94,3395.67 ; 2543.8,3095.96 C48.1@2596.46,3043.31 ; C48.1@2596.46,3031.5 C52.1@2596.46,2972.44 2635.83,2933.07 2657.48,2933.07 v1(2677.17,2913.39) 2696.85,2893.7 U1.58@2696.85,2846.46 U1.57@2716.54,2846.46 ; U1.20@2637.8,2409.45 2637.8,2362.2 2647.64,2352.36 2687.01,2352.36 2696.85,2362.2 U1.23@2696.85,2409.45 2696.85,2460.63 2716.54,2480.32 2736.22,2460.63 U1.25@2736.22,2409.45 ; 2795.28,2746.06 U1.53@2795.28,2846.46 2795.28,2887.39 2831.11,2923.23 2866.14,2923.23 C54.2@2915.35,2972.44 ; 2839.57,2495.08 2874.02,2460.63 U1.32@2874.02,2409.45 C62.1@2968.5,2409.45 ; U6.5@3255.91,3098.43 3320.87,3098.43 C44.2@3326.77,3092.52 C45.2@3385.83,3092.52 C46.2@3444.88,3092.52
  Top Layer w15: C65.2@2568.9,2166.34 2585.63,2183.07 C68.2@2667.32,2183.07 2706.69,2183.07 2782.48,2183.07 2805.12,2160.43 2827.76,2183.07 2931.1,2183.07 2970.47,2222.44 C62.1@2970.47,2411.42 C62.1@2968.5,2409.45 ; C48.1@2596.46,3031.5 C48.1@2596.46,3043.31 ; C54.2@2915.35,2972.44 C50.2@2915.35,3031.5
  Top Layer w20: 2440.94,3198.82 2543.8,3095.96 ; C50.2@2915.35,3031.5 2952.76,3031.5 v1(2992.13,2992.13) 3188.98,2992.13 3208.66,3011.81 3208.66,3041.34 3255.91,3088.58 U6.5@3255.91,3098.43
  Top Layer w30: 2440.94,3395.67 2549.21,3503.94
  Top Layer w40: 2549.21,3503.94 2599.21,3503.94 ; 2716.54,2480.32 2824.8,2480.32 2839.57,2495.08 2854.33,2509.84 2854.33,2687.01 2795.28,2746.06
  Bottom Layer w40: ELECTRODES_1.20@1548.43,1625 1615.16,1625 1653.54,1663.39 1653.54,1722.44 ; ELECTRODES_1.18@1548.43,1725 1650.98,1725 1653.54,1722.44 ; ELECTRODES_1.16@1548.43,1825 1649.41,1825 1653.54,1820.87 ; ELECTRODES_1.14@1548.43,1925 1649.41,1925 1653.54,1929.13 ; ELECTRODES_1.12@1548.43,2025 1650.98,2025 ; ELECTRODES_1.10@1548.43,2125 1649.41,2125 ; ELECTRODES_1.8@1548.43,2225 1649.41,2225 ; ELECTRODES_1.6@1548.43,2325 1649.41,2325 ; ELECTRODES_1.4@1548.43,2425 1649.41,2425 ; ELECTRODES_1.2@1548.43,2525 1650.98,2525 ; ELECTRODES_2.20@1550,2675 1652.56,2675 ; ELECTRODES_2.18@1550,2775 1650.98,2775 ; ELECTRODES_2.16@1550,2875 1650.98,2875 ; ELECTRODES_2.14@1550,2975 1652.56,2975 ; ELECTRODES_2.12@1550,3075 1652.56,3075 ; ELECTRODES_2.10@1550,3175 1650.98,3175 ; ELECTRODES_2.8@1550,3275 1650.98,3275 ; ELECTRODES_2.6@1550,3375 1652.56,3375 ; ELECTRODES_2.4@1550,3475 1652.95,3475 1653.54,3474.41 ; ELECTRODES_2.2@1550,3575 1602.17,3575 1653.54,3626.38 ; 2599.21,3503.94 2549.21,3503.94 2372.05,3681.1 1708.27,3681.1 1653.54,3626.38 ; v1(2677.17,2913.39) 2736.22,2972.44 2972.44,2972.44 v1(2992.13,2992.13) ; 1653.54,1722.44 1653.54,1820.87 ; 1653.54,1820.87 1653.54,1929.13 ; 1653.54,1929.13 1653.54,3474.41 ; 1653.54,3474.41 1653.54,3626.38
-5V_UNREG: C36.1 C37.1 C42.2 C43.2 U4.1 U6.2 U6.3 | length 691.3
  Top Layer w15: C42.2@3041.34,3029.53 3090.55,3029.53 3096.46,3023.62 U6.3@3161.42,3023.62 U6.2@3161.42,3061.02 3188.98,3061.02 3208.66,3080.71 3208.66,3208.66 ; U4.1@3246.06,3324.8 3246.06,3295.28 3208.66,3257.87 3208.66,3208.66 ; C37.1@3314.96,3248.03 3314.96,3216.54 3287.4,3188.98 3228.35,3188.98 3208.66,3208.66
  Top Layer w20: C37.1@3314.96,3248.03 C36.1@3314.96,3307.09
